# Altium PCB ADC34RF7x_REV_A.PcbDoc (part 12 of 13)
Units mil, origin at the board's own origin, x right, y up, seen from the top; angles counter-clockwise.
Board outline 6250 x 2716.54 mil, 18 copper layers (Top Layer, L2 GND, L3 PWR, L4 GND, L5 PWR/SIG, L6 GND, L7 SIGNAL, L8 GND, L9 GND, L10 SIGNAL, L11 GND, L12 SIGNAL, L13 GND, L14 PWR, L15 GND, L16 PWR/SIG, L16 GND, Bottom Layer), stack 95.314 mil thick; 668 components, 786 nets, 3150 pads, 2020 vias.
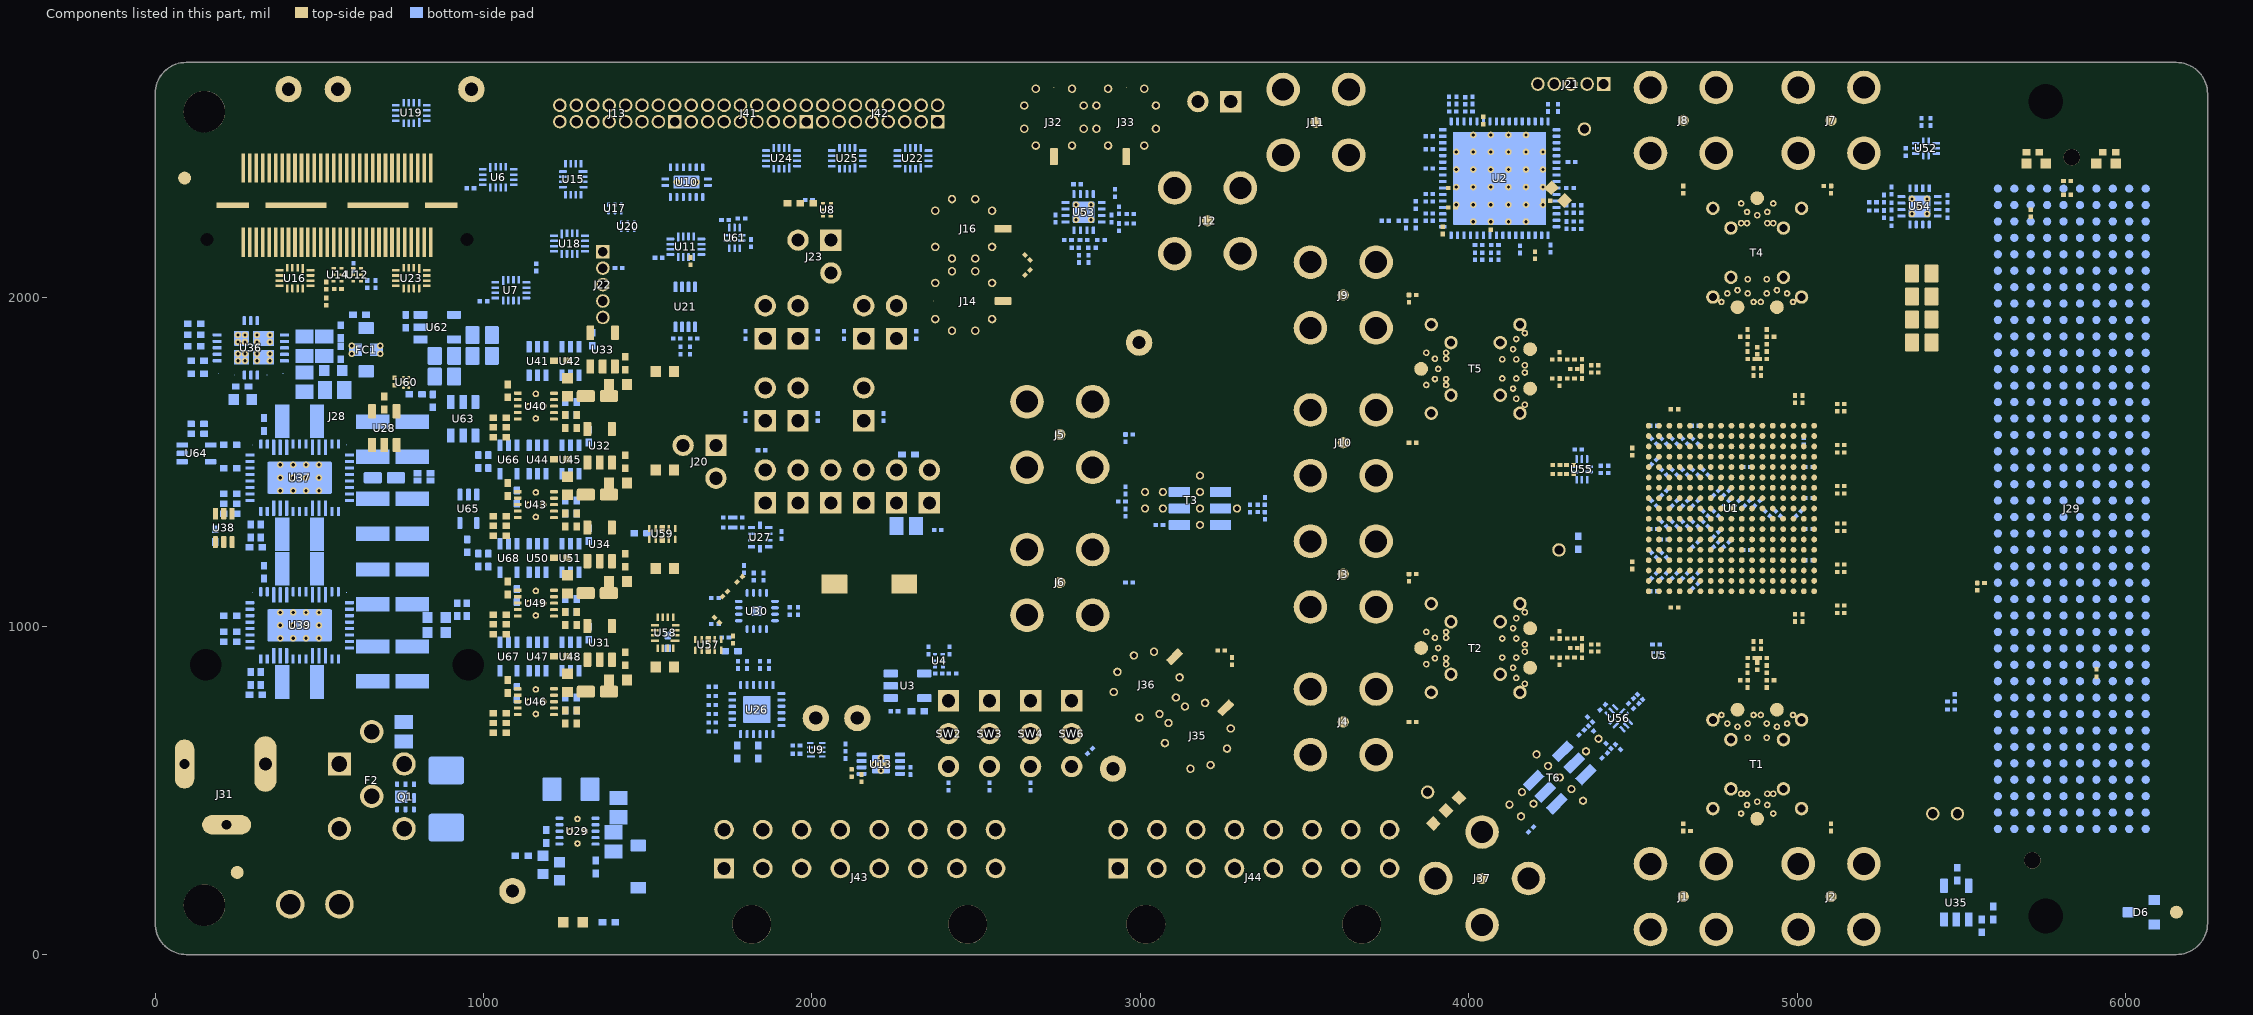
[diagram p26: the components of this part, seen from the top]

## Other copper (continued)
L12 SIGNAL:
  pour cut-out: 1882.62,2561.22 cw(c1882.62,2586.06) 1857.78,2586.06 cw(c1882.62,2586.06) 1882.62,2610.9 cw(c1882.62,2586.06) 1907.46,2586.06 cw(c1882.62,2586.06)
  pour cut-out: 2132.62,2561.22 cw(c2132.62,2586.06) 2107.79,2586.06 cw(c2132.62,2586.06) 2132.62,2610.9 cw(c2132.62,2586.06) 2157.46,2586.06 cw(c2132.62,2586.06)
  pour cut-out: 2082.62,2561.22 cw(c2082.62,2586.06) 2057.79,2586.06 cw(c2082.62,2586.06) 2082.62,2610.9 cw(c2082.62,2586.06) 2107.46,2586.06 cw(c2082.62,2586.06)
  pour cut-out: 1982.62,2561.22 cw(c1982.62,2586.06) 1957.78,2586.06 cw(c1982.62,2586.06) 1982.62,2610.9 cw(c1982.62,2586.06) 2007.46,2586.06 cw(c1982.62,2586.06)
  pour cut-out: 1932.62,2561.22 cw(c1932.62,2586.06) 1907.78,2586.06 cw(c1932.62,2586.06) 1932.62,2610.9 cw(c1932.62,2586.06) 1957.46,2586.06 cw(c1932.62,2586.06)
  pour cut-out: 4203.21,1668.47 cw(c4203.21,1679.47) 4192.21,1679.47 cw(c4203.21,1679.47) 4203.21,1690.47 cw(c4203.21,1679.47) 4214.21,1679.47 cw(c4203.21,1679.47)
  pour cut-out: 4972.22,1744.16 cw(c4972.22,1755.16) 4961.22,1755.16 cw(c4972.22,1755.16) 4972.22,1766.16 cw(c4972.22,1755.16) 4983.22,1755.16 cw(c4972.22,1755.16)
  pour cut-out: 5037.22,1704.16 cw(c5037.22,1715.16) 5026.22,1715.16 cw(c5037.22,1715.16) 5037.22,1726.16 cw(c5037.22,1715.16) 5048.22,1715.16 cw(c5037.22,1715.16)
  pour cut-out: 4972.22,1704.16 cw(c4972.22,1715.16) 4961.22,1715.16 cw(c4972.22,1715.16) 4972.22,1726.16 cw(c4972.22,1715.16) 4983.22,1715.16 cw(c4972.22,1715.16)
  pour cut-out: 4966.23,1665 cw(c4966.23,1676) 4955.23,1676 cw(c4966.23,1676) 4966.23,1687 cw(c4966.23,1676) 4977.23,1676 cw(c4966.23,1676)
  pour cut-out: 4972.22,950.38 cw(c4972.22,961.38) 4961.22,961.38 cw(c4972.22,961.38) 4972.22,972.38 cw(c4972.22,961.38) 4983.22,961.38 cw(c4972.22,961.38)
  pour cut-out: 4957.48,1018.28 cw(c4957.48,1029.28) 4946.48,1029.28 cw(c4957.48,1029.28) 4957.48,1040.28 cw(c4957.48,1029.28) 4968.48,1029.28 cw(c4957.48,1029.28)
  pour cut-out: 4956.83,1056.73 cw(c4956.83,1067.73) 4945.83,1067.73 cw(c4956.83,1067.73) 4956.83,1078.73 cw(c4956.83,1067.73) 4967.83,1067.73 cw(c4956.83,1067.73)
  pour cut-out: 2598.33,1683.28 ccw(c2655,1683.28) 2655,1626.61 ccw(c2655,1683.28) 2711.67,1683.28 ccw(c2655,1683.28) 2655,1739.95 ccw(c2655,1683.28)
  pour cut-out: 2798.33,1683.28 ccw(c2855,1683.28) 2855,1626.61 ccw(c2855,1683.28) 2911.67,1683.28 ccw(c2855,1683.28) 2855,1739.95 ccw(c2855,1683.28)
  pour cut-out: 4987.54,1976.16 cw(c4987.54,1987.16) 4976.54,1987.16 cw(c4987.54,1987.16) 4987.54,1998.16 cw(c4987.54,1987.16) 4998.54,1987.16 cw(c4987.54,1987.16)
  pour cut-out: 5861.42,921.27 cw(c5861.42,932.27) 5850.42,932.27 cw(c5861.42,932.27) 5861.42,943.27 cw(c5861.42,932.27) 5872.42,932.27 cw(c5861.42,932.27)
  pour cut-out: 3907,1965.23 cw(c3907,1976.23) 3896,1976.23 cw(c3907,1976.23) 3907,1987.23 cw(c3907,1976.23) 3918,1976.23 cw(c3907,1976.23)
  pour cut-out: 5003.52,19.66 ccw(c5003.52,76.33) 5060.19,76.33 ccw(c5003.52,76.33) 5003.52,132.99 ccw(c5003.52,76.33) 4946.85,76.33 ccw(c5003.52,76.33)
  pour cut-out: 5203.52,19.66 ccw(c5203.52,76.33) 5260.19,76.33 ccw(c5203.52,76.33) 5203.52,132.99 ccw(c5203.52,76.33) 5146.85,76.33 ccw(c5203.52,76.33)
  pour cut-out: 5003.52,219.66 ccw(c5003.52,276.33) 5060.19,276.33 ccw(c5003.52,276.33) 5003.52,332.99 ccw(c5003.52,276.33) 4946.85,276.33 ccw(c5003.52,276.33)
  pour cut-out: 5203.52,219.66 ccw(c5203.52,276.33) 5260.19,276.33 ccw(c5203.52,276.33) 5203.52,332.99 ccw(c5203.52,276.33) 5146.85,276.33 ccw(c5203.52,276.33)
  pour cut-out: 4301.79,1089.26 cw(c4301.79,1100.26) 4290.79,1100.26 cw(c4301.79,1100.26) 4301.79,1111.26 cw(c4301.79,1100.26) 4312.79,1100.26 cw(c4301.79,1100.26)
  pour cut-out: 5145.95,122.9 cw(c5145.95,133.9) 5134.95,133.9 cw(c5145.95,133.9) 5145.95,144.9 cw(c5145.95,133.9) 5156.95,133.9 cw(c5145.95,133.9)
  pour cut-out: 5961.42,1371.27 cw(c5961.42,1382.27) 5950.42,1382.27 cw(c5961.42,1382.27) 5961.42,1393.27 cw(c5961.42,1382.27) 5972.42,1382.27 cw(c5961.42,1382.27)
  pour cut-out: 5611.42,721.27 cw(c5611.42,732.27) 5600.42,732.27 cw(c5611.42,732.27) 5611.42,743.27 cw(c5611.42,732.27) 5622.42,732.27 cw(c5611.42,732.27)
  pour cut-out: 5661.42,921.27 cw(c5661.42,932.27) 5650.42,932.27 cw(c5661.42,932.27) 5661.42,943.27 cw(c5661.42,932.27) 5672.42,932.27 cw(c5661.42,932.27)
  pour cut-out: 5761.42,921.27 cw(c5761.42,932.27) 5750.42,932.27 cw(c5761.42,932.27) 5761.42,943.27 cw(c5761.42,932.27) 5772.42,932.27 cw(c5761.42,932.27)
  pour cut-out: 5145.97,2571.63 cw(c5145.97,2582.63) 5134.97,2582.63 cw(c5145.97,2582.63) 5145.97,2593.63 cw(c5145.97,2582.63) 5156.97,2582.63 cw(c5145.97,2582.63)
  pour cut-out: 5061.12,2571.63 cw(c5061.12,2582.63) 5050.12,2582.63 cw(c5061.12,2582.63) 5061.12,2593.63 cw(c5061.12,2582.63) 5072.12,2582.63 cw(c5061.12,2582.63)
  pour cut-out: 4695.97,2571.63 cw(c4695.97,2582.63) 4684.97,2582.63 cw(c4695.97,2582.63) 4695.97,2593.63 cw(c4695.97,2582.63) 4706.97,2582.63 cw(c4695.97,2582.63)
  pour cut-out: 4611.12,2571.63 cw(c4611.12,2582.63) 4600.12,2582.63 cw(c4611.12,2582.63) 4611.12,2593.63 cw(c4611.12,2582.63) 4622.12,2582.63 cw(c4611.12,2582.63)
  pour cut-out: 5061.12,2486.78 cw(c5061.12,2497.78) 5050.12,2497.78 cw(c5061.12,2497.78) 5061.12,2508.78 cw(c5061.12,2497.78) 5072.12,2497.78 cw(c5061.12,2497.78)
  pour cut-out: 4685.31,2467.62 cw(c4685.31,2478.62) 4674.31,2478.62 cw(c4685.31,2478.62) 4685.31,2489.62 cw(c4685.31,2478.62) 4696.31,2478.62 cw(c4685.31,2478.62)
  pour cut-out: 4685.58,2332.87 cw(c4685.58,2343.87) 4674.58,2343.87 cw(c4685.58,2343.87) 4685.58,2354.87 cw(c4685.58,2343.87) 4696.58,2343.87 cw(c4685.58,2343.87)
  pour cut-out: 4978.11,1935.7 cw(c4978.11,1946.7) 4967.11,1946.7 cw(c4978.11,1946.7) 4978.11,1957.7 cw(c4978.11,1946.7) 4989.11,1946.7 cw(c4978.11,1946.7)
  pour cut-out: 5203.54,2383.54 ccw(c5203.54,2440.21) 5260.21,2440.21 ccw(c5203.54,2440.21) 5203.54,2496.87 ccw(c5203.54,2440.21) 5146.88,2440.21 ccw(c5203.54,2440.21)
  pour cut-out: 5003.54,2383.54 ccw(c5003.54,2440.21) 5060.21,2440.21 ccw(c5003.54,2440.21) 5003.54,2496.87 ccw(c5003.54,2440.21) 4946.88,2440.21 ccw(c5003.54,2440.21)
  pour cut-out: 4753.54,2383.54 ccw(c4753.54,2440.21) 4810.21,2440.21 ccw(c4753.54,2440.21) 4753.54,2496.87 ccw(c4753.54,2440.21) 4696.88,2440.21 ccw(c4753.54,2440.21)
  pour cut-out: 4553.54,2383.54 ccw(c4553.54,2440.21) 4610.21,2440.21 ccw(c4553.54,2440.21) 4553.54,2496.87 ccw(c4553.54,2440.21) 4496.88,2440.21 ccw(c4553.54,2440.21)
  pour cut-out: 3048.15,2334.21 ccw(c3104.82,2334.21) 3104.82,2277.54 ccw(c3104.82,2334.21) 3161.48,2334.21 ccw(c3104.82,2334.21) 3104.82,2390.87 ccw(c3104.82,2334.21)
  pour cut-out: 3048.15,2134.21 ccw(c3104.82,2134.21) 3104.82,2077.54 ccw(c3104.82,2134.21) 3161.48,2134.21 ccw(c3104.82,2134.21) 3104.82,2190.87 ccw(c3104.82,2134.21)
  pour cut-out: 3461.4,1908.27 ccw(c3518.06,1908.27) 3518.06,1851.6 ccw(c3518.06,1908.27) 3574.73,1908.27 ccw(c3518.06,1908.27) 3518.06,1964.93 ccw(c3518.06,1908.27)
  pour cut-out: 3661.4,1908.27 ccw(c3718.06,1908.27) 3718.06,1851.6 ccw(c3718.06,1908.27) 3774.73,1908.27 ccw(c3718.06,1908.27) 3718.06,1964.93 ccw(c3718.06,1908.27)
  pour cut-out: 5051.97,1599.24 cw(c5051.97,1610.24) 5040.97,1610.24 cw(c5051.97,1610.24) 5051.97,1621.24 cw(c5051.97,1610.24) 5062.97,1610.24 cw(c5051.97,1610.24)
  pour cut-out: 4957.48,1599.24 cw(c4957.48,1610.24) 4946.48,1610.24 cw(c4957.48,1610.24) 4957.48,1621.24 cw(c4957.48,1610.24) 4968.48,1610.24 cw(c4957.48,1610.24)
  pour cut-out: 4831.5,1315.77 cw(c4831.5,1326.77) 4820.5,1326.77 cw(c4831.5,1326.77) 4831.5,1337.77 cw(c4831.5,1326.77) 4842.5,1326.77 cw(c4831.5,1326.77)
  pour cut-out: 4768.5,1252.78 cw(c4768.5,1263.78) 4757.5,1263.78 cw(c4768.5,1263.78) 4768.5,1274.78 cw(c4768.5,1263.78) 4779.5,1263.78 cw(c4768.5,1263.78)
  pour cut-out: 4768.5,1284.28 cw(c4768.5,1295.28) 4757.5,1295.28 cw(c4768.5,1295.28) 4768.5,1306.28 cw(c4768.5,1295.28) 4779.5,1295.28 cw(c4768.5,1295.28)
  pour cut-out: 4768.5,1315.77 cw(c4768.5,1326.77) 4757.5,1326.77 cw(c4768.5,1326.77) 4768.5,1337.77 cw(c4768.5,1326.77) 4779.5,1326.77 cw(c4768.5,1326.77)
  pour cut-out: 4768.5,1347.27 cw(c4768.5,1358.27) 4757.5,1358.27 cw(c4768.5,1358.27) 4768.5,1369.27 cw(c4768.5,1358.27) 4779.5,1358.27 cw(c4768.5,1358.27)
  pour cut-out: 4705.51,1599.24 cw(c4705.51,1610.24) 4694.51,1610.24 cw(c4705.51,1610.24) 4705.51,1621.24 cw(c4705.51,1610.24) 4716.51,1610.24 cw(c4705.51,1610.24)
  pour cut-out: 4642.52,1567.74 cw(c4642.52,1578.74) 4631.52,1578.74 cw(c4642.52,1578.74) 4642.52,1589.74 cw(c4642.52,1578.74) 4653.52,1578.74 cw(c4642.52,1578.74)
  pour cut-out: 4611.02,1473.25 cw(c4611.02,1484.25) 4600.02,1484.25 cw(c4611.02,1484.25) 4611.02,1495.25 cw(c4611.02,1484.25) 4622.02,1484.25 cw(c4611.02,1484.25)
  pour cut-out: 4611.02,1410.26 cw(c4611.02,1421.26) 4600.02,1421.26 cw(c4611.02,1421.26) 4611.02,1432.26 cw(c4611.02,1421.26) 4622.02,1421.26 cw(c4611.02,1421.26)
  pour cut-out: 4611.02,1378.76 cw(c4611.02,1389.76) 4600.02,1389.76 cw(c4611.02,1389.76) 4611.02,1400.76 cw(c4611.02,1389.76) 4622.02,1389.76 cw(c4611.02,1389.76)
  pour cut-out: 4473.75,1293.02 cw(c4473.75,1304.02) 4462.75,1304.02 cw(c4473.75,1304.02) 4473.75,1315.02 cw(c4473.75,1304.02) 4484.75,1304.02 cw(c4473.75,1304.02)
  pour cut-out: 4426.57,1295.82 cw(c4426.57,1306.82) 4415.57,1306.82 cw(c4426.57,1306.82) 4426.57,1317.82 cw(c4426.57,1306.82) 4437.57,1306.82 cw(c4426.57,1306.82)
  pour cut-out: 4298.27,1399.62 cw(c4298.27,1410.62) 4287.27,1410.62 cw(c4298.27,1410.62) 4298.27,1421.62 cw(c4298.27,1410.62) 4309.27,1410.62 cw(c4298.27,1410.62)
  pour cut-out: 4361.04,1832.03 cw(c4361.04,1843.03) 4350.04,1843.03 cw(c4361.04,1843.03) 4361.04,1854.03 cw(c4361.04,1843.03) 4372.04,1843.03 cw(c4361.04,1843.03)
  pour cut-out: 4301.79,1939.24 cw(c4301.79,1950.24) 4290.79,1950.24 cw(c4301.79,1950.24) 4301.79,1961.24 cw(c4301.79,1950.24) 4312.79,1950.24 cw(c4301.79,1950.24)
  pour cut-out: 4116.79,2029.31 cw(c4116.79,2040.31) 4105.79,2040.31 cw(c4116.79,2040.31) 4116.79,2051.31 cw(c4116.79,2040.31) 4127.79,2040.31 cw(c4116.79,2040.31)
  pour cut-out: 4156.1,2118.3 cw(c4156.1,2129.3) 4145.1,2129.3 cw(c4156.1,2129.3) 4156.1,2140.3 cw(c4156.1,2129.3) 4167.1,2129.3 cw(c4156.1,2129.3)
  pour cut-out: 3558.06,1997.27 cw(c3558.06,2008.27) 3547.06,2008.27 cw(c3558.06,2008.27) 3558.06,2019.27 cw(c3558.06,2008.27) 3569.06,2008.27 cw(c3558.06,2008.27)
  pour cut-out: 3661.4,1658.27 ccw(c3718.06,1658.27) 3718.06,1601.6 ccw(c3718.06,1658.27) 3774.73,1658.27 ccw(c3718.06,1658.27) 3718.06,1714.93 ccw(c3718.06,1658.27)
  pour cut-out: 4170,1320 3972.53,1517.47 3972.53,1518.81 4190.26,1518.81 4178.47,1507.02 4178.47,1326.77
  text ".Layer_Name" at 575,-860 h60
L10 SIGNAL:
  pour cut-out: 3897.11,1741.27 cw(c3897.11,1752.27) 3886.11,1752.27 cw(c3897.11,1752.27) 3897.11,1763.27 cw(c3897.11,1752.27) 3908.11,1752.27 cw(c3897.11,1752.27)
  pour cut-out: 3931.11,1741.27 cw(c3931.11,1752.27) 3920.11,1752.27 cw(c3931.11,1752.27) 3931.11,1763.27 cw(c3931.11,1752.27) 3942.11,1752.27 cw(c3931.11,1752.27)
  pour cut-out: 3898.08,1738.93 cw(c3898.08,1749.93) 3887.08,1749.93 cw(c3898.08,1749.93) 3898.08,1760.93 cw(c3898.08,1749.93) 3909.08,1749.93 cw(c3898.08,1749.93)
  pour cut-out: 3897.11,1803.27 cw(c3897.11,1814.27) 3886.11,1814.27 cw(c3897.11,1814.27) 3897.11,1825.27 cw(c3897.11,1814.27) 3908.11,1814.27 cw(c3897.11,1814.27)
  pour cut-out: 3931.11,1803.27 cw(c3931.11,1814.27) 3920.11,1814.27 cw(c3931.11,1814.27) 3931.11,1825.27 cw(c3931.11,1814.27) 3942.11,1814.27 cw(c3931.11,1814.27)
  pour cut-out: 4135.11,1712.27 cw(c4135.11,1723.27) 4124.11,1723.27 cw(c4135.11,1723.27) 4135.11,1734.27 cw(c4135.11,1723.27) 4146.11,1723.27 cw(c4135.11,1723.27)
  pour cut-out: 4171.11,1761.27 cw(c4171.11,1772.27) 4160.11,1772.27 cw(c4171.11,1772.27) 4171.11,1783.27 cw(c4171.11,1772.27) 4182.11,1772.27 cw(c4171.11,1772.27)
  pour cut-out: 4135.11,1832.27 cw(c4135.11,1843.27) 4124.11,1843.27 cw(c4135.11,1843.27) 4135.11,1854.27 cw(c4135.11,1843.27) 4146.11,1843.27 cw(c4135.11,1843.27)
  pour cut-out: 3378.15,2634.21 ccw(c3434.82,2634.21) 3434.82,2577.54 ccw(c3434.82,2634.21) 3491.48,2634.21 ccw(c3434.82,2634.21) 3434.82,2690.87 ccw(c3434.82,2634.21)
  pour cut-out: 3578.15,2634.21 ccw(c3634.82,2634.21) 3634.82,2577.54 ccw(c3634.82,2634.21) 3691.48,2634.21 ccw(c3634.82,2634.21) 3634.82,2690.87 ccw(c3634.82,2634.21)
  pour cut-out: 4433.78,1367.21 cw(c4433.78,1378.21) 4422.78,1378.21 cw(c4433.78,1378.21) 4433.78,1389.21 cw(c4433.78,1378.21) 4444.78,1378.21 cw(c4433.78,1378.21)
  pour cut-out: 4696.88,2640.21 ccw(c4753.54,2640.21) 4753.54,2583.54 ccw(c4753.54,2640.21) 4810.21,2640.21 ccw(c4753.54,2640.21) 4753.54,2696.87 ccw(c4753.54,2640.21)
  pour cut-out: 4496.88,2640.21 ccw(c4553.54,2640.21) 4553.54,2583.54 ccw(c4553.54,2640.21) 4610.21,2640.21 ccw(c4553.54,2640.21) 4553.54,2696.87 ccw(c4553.54,2640.21)
  pour cut-out: 5861.42,2321.27 cw(c5861.42,2332.27) 5850.42,2332.27 cw(c5861.42,2332.27) 5861.42,2343.27 cw(c5861.42,2332.27) 5872.42,2332.27 cw(c5861.42,2332.27)
  pour cut-out: 5811.42,2221.27 cw(c5811.42,2232.27) 5800.42,2232.27 cw(c5811.42,2232.27) 5811.42,2243.27 cw(c5811.42,2232.27) 5822.42,2232.27 cw(c5811.42,2232.27)
  pour cut-out: 5861.42,2121.27 cw(c5861.42,2132.27) 5850.42,2132.27 cw(c5861.42,2132.27) 5861.42,2143.27 cw(c5861.42,2132.27) 5872.42,2132.27 cw(c5861.42,2132.27)
  pour cut-out: 5961.42,1971.27 cw(c5961.42,1982.27) 5950.42,1982.27 cw(c5961.42,1982.27) 5961.42,1993.27 cw(c5961.42,1982.27) 5972.42,1982.27 cw(c5961.42,1982.27)
  pour cut-out: 6061.42,1921.27 cw(c6061.42,1932.27) 6050.42,1932.27 cw(c6061.42,1932.27) 6061.42,1943.27 cw(c6061.42,1932.27) 6072.42,1932.27 cw(c6061.42,1932.27)
  pour cut-out: 6061.42,1971.27 cw(c6061.42,1982.27) 6050.42,1982.27 cw(c6061.42,1982.27) 6061.42,1993.27 cw(c6061.42,1982.27) 6072.42,1982.27 cw(c6061.42,1982.27)
  pour cut-out: 6061.42,2121.27 cw(c6061.42,2132.27) 6050.42,2132.27 cw(c6061.42,2132.27) 6061.42,2143.27 cw(c6061.42,2132.27) 6072.42,2132.27 cw(c6061.42,2132.27)
  pour cut-out: 6061.42,2171.27 cw(c6061.42,2182.27) 6050.42,2182.27 cw(c6061.42,2182.27) 6061.42,2193.27 cw(c6061.42,2182.27) 6072.42,2182.27 cw(c6061.42,2182.27)
  pour cut-out: 6061.42,2321.27 cw(c6061.42,2332.27) 6050.42,2332.27 cw(c6061.42,2332.27) 6061.42,2343.27 cw(c6061.42,2332.27) 6072.42,2332.27 cw(c6061.42,2332.27)
  pour cut-out: 5061.12,2571.63 cw(c5061.12,2582.63) 5050.12,2582.63 cw(c5061.12,2582.63) 5061.12,2593.63 cw(c5061.12,2582.63) 5072.12,2582.63 cw(c5061.12,2582.63)
  pour cut-out: 5145.97,2571.63 cw(c5145.97,2582.63) 5134.97,2582.63 cw(c5145.97,2582.63) 5145.97,2593.63 cw(c5145.97,2582.63) 5156.97,2582.63 cw(c5145.97,2582.63)
  pour cut-out: 4695.97,2571.63 cw(c4695.97,2582.63) 4684.97,2582.63 cw(c4695.97,2582.63) 4695.97,2593.63 cw(c4695.97,2582.63) 4706.97,2582.63 cw(c4695.97,2582.63)
  pour cut-out: 4611.12,2571.63 cw(c4611.12,2582.63) 4600.12,2582.63 cw(c4611.12,2582.63) 4611.12,2593.63 cw(c4611.12,2582.63) 4622.12,2582.63 cw(c4611.12,2582.63)
  pour cut-out: 4361.07,2573.95 cw(c4361.07,2584.95) 4350.07,2584.95 cw(c4361.07,2584.95) 4361.07,2595.95 cw(c4361.07,2584.95) 4372.07,2584.95 cw(c4361.07,2584.95)
  pour cut-out: 1214.61,709.43 cw(c1214.61,720.43) 1203.61,720.43 cw(c1214.61,720.43) 1214.61,731.43 cw(c1214.61,720.43) 1225.61,720.43 cw(c1214.61,720.43)
  pour cut-out: 1431.18,909.24 cw(c1431.18,920.24) 1420.18,920.24 cw(c1431.18,920.24) 1431.18,931.24 cw(c1431.18,920.24) 1442.18,920.24 cw(c1431.18,920.24)
  pour cut-out: 1214.61,1009.43 cw(c1214.61,1020.43) 1203.61,1020.43 cw(c1214.61,1020.43) 1214.61,1031.43 cw(c1214.61,1020.43) 1225.61,1020.43 cw(c1214.61,1020.43)
  pour cut-out: 1214.61,1309.43 cw(c1214.61,1320.43) 1203.61,1320.43 cw(c1214.61,1320.43) 1214.61,1331.43 cw(c1214.61,1320.43) 1225.61,1320.43 cw(c1214.61,1320.43)
  pour cut-out: 1214.61,1609.43 cw(c1214.61,1620.43) 1203.61,1620.43 cw(c1214.61,1620.43) 1214.61,1631.43 cw(c1214.61,1620.43) 1225.61,1620.43 cw(c1214.61,1620.43)
  pour cut-out: 4946.85,76.33 ccw(c5003.52,76.33) 5003.52,19.66 ccw(c5003.52,76.33) 5060.19,76.33 ccw(c5003.52,76.33) 5003.52,132.99 ccw(c5003.52,76.33)
  pour cut-out: 5146.85,76.33 ccw(c5203.52,76.33) 5203.52,19.66 ccw(c5203.52,76.33) 5260.19,76.33 ccw(c5203.52,76.33) 5203.52,132.99 ccw(c5203.52,76.33)
  pour cut-out: 4946.85,276.33 ccw(c5003.52,276.33) 5003.52,219.66 ccw(c5003.52,276.33) 5060.19,276.33 ccw(c5003.52,276.33) 5003.52,332.99 ccw(c5003.52,276.33)
  pour cut-out: 5146.85,276.33 ccw(c5203.52,276.33) 5203.52,219.66 ccw(c5203.52,276.33) 5260.19,276.33 ccw(c5203.52,276.33) 5203.52,332.99 ccw(c5203.52,276.33)
  pour cut-out: 3661.4,1658.27 ccw(c3718.06,1658.27) 3718.06,1601.6 ccw(c3718.06,1658.27) 3774.73,1658.27 ccw(c3718.06,1658.27) 3718.06,1714.93 ccw(c3718.06,1658.27)
  pour cut-out: 3555.09,1382.97 cw(c3555.09,1393.97) 3544.09,1393.97 cw(c3555.09,1393.97) 3555.09,1404.97 cw(c3555.09,1393.97) 3566.09,1393.97 cw(c3555.09,1393.97)
  pour cut-out: 3475.09,1382.97 cw(c3475.09,1393.97) 3464.09,1393.97 cw(c3475.09,1393.97) 3475.09,1404.97 cw(c3475.09,1393.97) 3486.09,1393.97 cw(c3475.09,1393.97)
  pour cut-out: 3461.4,1908.27 ccw(c3518.06,1908.27) 3518.06,1851.6 ccw(c3518.06,1908.27) 3574.73,1908.27 ccw(c3518.06,1908.27) 3518.06,1964.93 ccw(c3518.06,1908.27)
  pour cut-out: 3661.4,1908.27 ccw(c3718.06,1908.27) 3718.06,1851.6 ccw(c3718.06,1908.27) 3774.73,1908.27 ccw(c3718.06,1908.27) 3718.06,1964.93 ccw(c3718.06,1908.27)
  pour cut-out: 3661.4,1258.29 ccw(c3718.06,1258.29) 3718.06,1201.62 ccw(c3718.06,1258.29) 3774.73,1258.29 ccw(c3718.06,1258.29) 3718.06,1314.96 ccw(c3718.06,1258.29)
  pour cut-out: 3461.4,1258.29 ccw(c3518.06,1258.29) 3518.06,1201.62 ccw(c3518.06,1258.29) 3574.73,1258.29 ccw(c3518.06,1258.29) 3518.06,1314.96 ccw(c3518.06,1258.29)
  pour cut-out: 3661.4,1458.27 ccw(c3718.06,1458.27) 3718.06,1401.6 ccw(c3718.06,1458.27) 3774.73,1458.27 ccw(c3718.06,1458.27) 3718.06,1514.93 ccw(c3718.06,1458.27)
  pour cut-out: 3461.4,1458.27 ccw(c3518.06,1458.27) 3518.06,1401.6 ccw(c3518.06,1458.27) 3574.73,1458.27 ccw(c3518.06,1458.27) 3518.06,1514.93 ccw(c3518.06,1458.27)
  pour cut-out: 3461.4,1658.27 ccw(c3518.06,1658.27) 3518.06,1601.6 ccw(c3518.06,1658.27) 3574.73,1658.27 ccw(c3518.06,1658.27) 3518.06,1714.93 ccw(c3518.06,1658.27)
  pour cut-out: 5020.47,1126.8 cw(c5020.47,1137.8) 5009.47,1137.8 cw(c5020.47,1137.8) 5020.47,1148.8 cw(c5020.47,1137.8) 5031.47,1137.8 cw(c5020.47,1137.8)
  pour cut-out: 5020.47,1567.74 cw(c5020.47,1578.74) 5009.47,1578.74 cw(c5020.47,1578.74) 5020.47,1589.74 cw(c5020.47,1578.74) 5031.47,1578.74 cw(c5020.47,1578.74)
  pour cut-out: 4768.5,1347.27 cw(c4768.5,1358.27) 4757.5,1358.27 cw(c4768.5,1358.27) 4768.5,1369.27 cw(c4768.5,1358.27) 4779.5,1358.27 cw(c4768.5,1358.27)
  pour cut-out: 4610.44,1126.53 cw(c4610.44,1137.53) 4599.44,1137.53 cw(c4610.44,1137.53) 4610.44,1148.53 cw(c4610.44,1137.53) 4621.44,1137.53 cw(c4610.44,1137.53)
  pour cut-out: 4674.02,1126.8 cw(c4674.02,1137.8) 4663.02,1137.8 cw(c4674.02,1137.8) 4674.02,1148.8 cw(c4674.02,1137.8) 4685.02,1137.8 cw(c4674.02,1137.8)
  pour cut-out: 4426.57,1295.82 cw(c4426.57,1306.82) 4415.57,1306.82 cw(c4426.57,1306.82) 4426.57,1317.82 cw(c4426.57,1306.82) 4437.57,1306.82 cw(c4426.57,1306.82)
  pour cut-out: 4705.51,1599.24 cw(c4705.51,1610.24) 4694.51,1610.24 cw(c4705.51,1610.24) 4705.51,1621.24 cw(c4705.51,1610.24) 4716.51,1610.24 cw(c4705.51,1610.24)
  pour cut-out: 4548.03,1567.74 cw(c4548.03,1578.74) 4537.03,1578.74 cw(c4548.03,1578.74) 4548.03,1589.74 cw(c4548.03,1578.74) 4559.03,1578.74 cw(c4548.03,1578.74)
  pour cut-out: 4685.58,2179.41 cw(c4685.58,2190.41) 4674.58,2190.41 cw(c4685.58,2190.41) 4685.58,2201.41 cw(c4685.58,2190.41) 4696.58,2190.41 cw(c4685.58,2190.41)
  pour cut-out: 4326.55,2323.15 cw(c4326.55,2334.15) 4315.55,2334.15 cw(c4326.55,2334.15) 4326.55,2345.15 cw(c4326.55,2334.15) 4337.55,2334.15 cw(c4326.55,2334.15)
  pour cut-out: 3558.06,1997.27 cw(c3558.06,2008.27) 3547.06,2008.27 cw(c3558.06,2008.27) 3558.06,2019.27 cw(c3558.06,2008.27) 3569.06,2008.27 cw(c3558.06,2008.27)
  pour cut-out: 3618.06,1937.27 cw(c3618.06,1948.27) 3607.06,1948.27 cw(c3618.06,1948.27) 3618.06,1959.27 cw(c3618.06,1948.27) 3629.06,1948.27 cw(c3618.06,1948.27)
  pour cut-out: 3660.49,1954.84 cw(c3660.49,1965.84) 3649.49,1965.84 cw(c3660.49,1965.84) 3660.49,1976.84 cw(c3660.49,1965.84) 3671.49,1965.84 cw(c3660.49,1965.84)
  pour cut-out: 3775.26,1965.23 cw(c3775.26,1976.23) 3764.26,1976.23 cw(c3775.26,1976.23) 3775.26,1987.23 cw(c3775.26,1976.23) 3786.26,1976.23 cw(c3775.26,1976.23)
  pour cut-out: 3786.02,1944.05 cw(c3786.02,1955.05) 3775.02,1955.05 cw(c3786.02,1955.05) 3786.02,1966.05 cw(c3786.02,1955.05) 3797.02,1955.05 cw(c3786.02,1955.05)
  pour cut-out: 3907,1965.23 cw(c3907,1976.23) 3896,1976.23 cw(c3907,1976.23) 3907,1987.23 cw(c3907,1976.23) 3918,1976.23 cw(c3907,1976.23)
  pour cut-out: 3987,1965.23 cw(c3987,1976.23) 3976,1976.23 cw(c3987,1976.23) 3987,1987.23 cw(c3987,1976.23) 3998,1976.23 cw(c3987,1976.23)
  pour cut-out: 4067,1965.23 cw(c4067,1976.23) 4056,1976.23 cw(c4067,1976.23) 4067,1987.23 cw(c4067,1976.23) 4078,1976.23 cw(c4067,1976.23)
  pour cut-out: 4234.52,1773.09 cw(c4234.52,1784.09) 4223.52,1784.09 cw(c4234.52,1784.09) 4234.52,1795.09 cw(c4234.52,1784.09) 4245.52,1784.09 cw(c4234.52,1784.09)
  pour cut-out: 4200.97,1788.43 cw(c4200.97,1799.43) 4189.97,1799.43 cw(c4200.97,1799.43) 4200.97,1810.43 cw(c4200.97,1799.43) 4211.97,1799.43 cw(c4200.97,1799.43)
  pour cut-out: 4134.52,1579.31 cw(c4134.52,1590.31) 4123.52,1590.31 cw(c4134.52,1590.31) 4134.52,1601.31 cw(c4134.52,1590.31) 4145.52,1590.31 cw(c4134.52,1590.31)
  pour cut-out: 4054.52,1579.31 cw(c4054.52,1590.31) 4043.52,1590.31 cw(c4054.52,1590.31) 4054.52,1601.31 cw(c4054.52,1590.31) 4065.52,1590.31 cw(c4054.52,1590.31)
  pour cut-out: 3974.52,1579.31 cw(c3974.52,1590.31) 3963.52,1590.31 cw(c3974.52,1590.31) 3974.52,1601.31 cw(c3974.52,1590.31) 3985.52,1590.31 cw(c3974.52,1590.31)
  pour cut-out: 3894.52,1579.31 cw(c3894.52,1590.31) 3883.52,1590.31 cw(c3894.52,1590.31) 3894.52,1601.31 cw(c3894.52,1590.31) 3905.52,1590.31 cw(c3894.52,1590.31)
  pour cut-out: 3779.86,1579.31 cw(c3779.86,1590.31) 3768.86,1590.31 cw(c3779.86,1590.31) 3779.86,1601.31 cw(c3779.86,1590.31) 3790.86,1590.31 cw(c3779.86,1590.31)
  pour cut-out: 3699.86,1579.31 cw(c3699.86,1590.31) 3688.86,1590.31 cw(c3699.86,1590.31) 3699.86,1601.31 cw(c3699.86,1590.31) 3710.86,1590.31 cw(c3699.86,1590.31)
  pour cut-out: 1802,1782 1802,2186.87 2541.03,2186.87 2541.03,2186.1
  pour cut-out: 1930,2270 1932.62,2267.38 1932.62,2175.08 2057.48,2175.08 2057.76,2175.36 1960.34,2272.78 1932.62,2272.78
  pour cut-out: 1175.35,2162.13 1930.89,2162.13 1930.89,2505.56 2390.45,2505.56 2390.45,2626.34 1175.35,2626.34
  pour cut-out: 1800,2050 1643.82,2206.18 1805.73,2206.18
  text ".Layer_Name" at 575,-860 h60
L11 GND:
  text ".Layer_Name" at 575,-860 h60
L13 GND:
  text ".Layer_Name" at 575,-860 h60
Bottom Layer:
  drawing of 87 lines, arcs and shapes, not listed
  text ".Layer_Name" at 577,-858.49 h60
Multi-Layer:
  pour cut-out: 3186.77,2234.21 ccw(c3204.82,2234.21) 3204.82,2216.16 ccw(c3204.82,2234.21) 3222.86,2234.21 ccw(c3204.82,2234.21) 3204.82,2252.25 ccw(c3204.82,2234.21)
  pour cut-out: 3516.77,2534.21 ccw(c3534.82,2534.21) 3534.82,2516.16 ccw(c3534.82,2534.21) 3552.86,2534.21 ccw(c3534.82,2534.21) 3534.82,2552.25 ccw(c3534.82,2534.21)
  pour cut-out: 2736.96,1583.28 ccw(c2755,1583.28) 2755,1565.23 ccw(c2755,1583.28) 2773.04,1583.28 ccw(c2755,1583.28) 2755,1601.32 ccw(c2755,1583.28)
  pour cut-out: 2736.96,1133.28 ccw(c2755,1133.28) 2755,1115.23 ccw(c2755,1133.28) 2773.04,1133.28 ccw(c2755,1133.28) 2755,1151.32 ccw(c2755,1133.28)
  pour cut-out: 4022.7,231.61 ccw(c4040.75,231.61) 4040.75,213.57 ccw(c4040.75,231.61) 4058.79,231.61 ccw(c4040.75,231.61) 4040.75,249.66 ccw(c4040.75,231.61)

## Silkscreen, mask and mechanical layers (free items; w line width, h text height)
Top Overlay:
  drawing of 157 lines, arcs and shapes, not listed
  text "LMK SPI" at 3961.29,2634.21 h25
  text "<-GND" at 2425.78,2569.08 h25
  text "GND->" at 1066.12,2566.54 h25
  text "Power Supply OK" at 5494.27,2341 h25
  text "DUT OPTION" at 5320,2105 h100
  text "ADC SPI" at 1114.17,2073.52 h25
  text "ADC34RF72" at 5455,2045 h50
  text "ADC34RF75" at 5455,1975 h50
  text "ADC32RF77" at 5455,1905 h50
  text "Other" at 5455,1835 h50
  text "GPIOVDD" at 1561.4,1654.84 h25
  text "FPGA to ADC" at 2369.72,855.04 h25
  text "3.3V" at 2742.94,854.43 h25
  text "ADC3xRF7x / RevA" at 3376.97,466.84 h60
  text "ADC to FPGA" at 2365.49,450.75 h25
  text "I2C VADJ" at 2741,421.68 h25
  text "VADJ" at 3985.19,408.16 h30 r45
  text "<- GND ->" at 2627.33,331.11 h25
  text "GND->" at 1520.86,328.55 h25
  text "GPIO" at 3885.07,309.5 h30 r45
  text "AVDD12" at 2278.53,190.01 h20
  text "AVDD18" at 2907.83,190.01 h20
  text "DVDD09" at 1685.9,186.52 h20
  text "AVDD12 / SNS" at 2486.89,151.03 h20
  text "AVDD18 / SNS" at 3096.34,151.03 h20
  text "CLK / VDD12" at 3343.68,148.9 h20
  text "CLK / VDD18" at 3579.9,148.9 h20
  text "DVDD / SNS+" at 2132.53,148.17 h20
  text "DVDD / SNS-" at 3214.42,148.17 h20
  text "CLK / VDD12 / SNS" at 3448.27,132.78 h20
  text "CLK / VDD18 / SNS" at 3684.49,132.78 h20
  text "CW" at 6110.58,34.15 h40
  text "Connector #1" at 1817.12,6.09 h25
  text "Connector #2" at 3017.12,6.09 h25
  text ".Layer_Name" at 577,-858.49 h60
Bottom Overlay:
  circle w10: c1740.4,684.59 r0.08
  lines w4: 2624.7,413.68 2613.7,421.68 ; 2624.7,429.68 2613.7,421.68 ; 2628.92,320.88 2617.92,328.88 ; 2628.92,336.88 2617.92,328.88 ; 2667.7,421.68 2613.7,421.68 ; 2671.92,328.88 2617.92,328.88 ; 2776.7,421.68 2830.7,421.68 ; 2780.92,328.88 2834.92,328.88 ; 2819.7,413.68 2830.7,421.68 ; 2819.7,429.68 2830.7,421.68 ; 2823.92,320.88 2834.92,328.88 ; 2823.92,336.88 2834.92,328.88
  lines w7: 990,1555 1005,1540 ; 1020,1555 1005,1540 ; 1040,1600 1005,1565 1005,1540
  text "OUTER / GNDS" at 2788.11,386.45 h25
  text "INNER / PWR" at 2786.31,296.55 h25
  text ".Layer_Name" at 577,-858.49 h60
Top Paste:
  text ".Layer_Name" at 577,-858.49 h60
Bottom Paste:
  text ".Layer_Name" at 577,-858.49 h60
Top Solder:
  text ".Layer_Name" at 577,-858.49 h60
  text ".Layer_Name" at 577,-858.49 h60
Bottom Solder:
  text ".Layer_Name" at 577,-858.49 h60
Drill Guide:
  text ".Layer_Name" at 577,-858.49 h60
M1 Board Outline:
  the board outline again, w10
  text ".Layer_Name" at 577,-858.49 h60
M2 Board Dimensions:
  rectangle: 125,-400 500,-275
  rectangle: 0,-275 125,-150
  lines w7: 0,-275 1000,-275 ; 125,-400 125,-150 ; 250,-400 250,-150 ; 500,-400 500,-150 ; 750,-400 750,-150 ; 0,-400 0,-150 1000,-150 1000,-400 0,-400
  text ".Layer_Name" at 577,-858.49 h60
M3 3D STEP Top:
  text ".Layer_Name" at 577,-858.49 h60
M4 3D STEP Bottom:
  text ".Layer_Name" at 577,-858.49 h60
M5 Assembly Top:
  lines w10: -292,-930.17 6308,-930.17 ; -292,-726.83 6310,-726.83 ; -292,-523.5 -292,-1133.5 3713,-1133.5 6310,-1133.5 6310,-523.5 -291.5,-523.5 -291.5,-1133.5 1284,-1133.5 ; 2173,-1133.5 2173,-523.5 ; 3440,-726.83 3440,-523.5 ; 4280,-726.83 4280,-523.5 ; 4902,-1140 4902,-937.17
  text "COMPONENTS MARKED 'DNP' SHOULD NOT BE POPULATED." at 1153.5,-318.5 h60
  text "ASSEMBLY VARIANT:" at 1153,-434 h60
  text ".VariantName" at 2189,-434 h60
  text "PCB VIEWED FROM TOP SIDE" at -228.5,-655.67 h60
  text "BOARD #:" at 2248,-655.67 h60
  text ".PRJ_Number" at 2793.5,-655.67 h60
  text "REV:" at 3638,-655.67 h60
  text ".PCB_Rev" at 3929.5,-655.67 h60
  text "SVN REV:" at 4476,-655.67 h60
  text ".VersionControl_RevNumber" at 4982,-655.67 h60
  text "PLOT NAME =" at -228.5,-1064.34 h60
  text ".plot_File_Name" at 577,-1064.34 h60
  text "GENERATED    :" at 2250,-1064.34 h60
  text ".Print_Date" at 3119.5,-1064.34 h60
  text ".Print_Time" at 3848.5,-1064.34 h60
  text "TEXAS INSTRUMENTS" at 5113,-1064.34 h60
M6 Assembly Bottom:
  lines w10: -292.5,-727.33 6309.5,-727.33 ; -290.5,-930.67 6309.5,-930.67 ; 1115.5,-1140.5 1115.5,-937.67 ; 1737.5,-727.33 1737.5,-524 ; 2577.5,-727.33 2577.5,-524 ; 3844.5,-1134 3844.5,-524 ; 4733.5,-1134 6309,-1134 6309,-524 -292.5,-524 -292.5,-1134 2304.5,-1134 6309.5,-1134 6309.5,-524
  text "COMPONENTS MARKED 'DNP' SHOULD NOT BE POPULATED." at 6102,-318 h60
  text ".VariantName" at 5058,-434 h60
  text "ASSEMBLY VARIANT:" at 6097,-434 h60
  text ".VersionControl_RevNumber" at 1035.5,-656.17 h60
  text "SVN REV:" at 1541.5,-656.17 h60
  text ".PCB_Rev" at 2088,-656.17 h60
  text "REV:" at 2379.5,-656.17 h60
  text ".PRJ_Number" at 3224,-656.17 h60
  text "BOARD #:" at 3769.5,-656.17 h60
  text "PCB VIEWED FROM BOTTOM SIDE" at 6246,-656.17 h60
  text "TEXAS INSTRUMENTS" at 904.5,-1064.84 h60
  text ".Print_Time" at 2169,-1064.84 h60
  text ".Print_Date" at 2898,-1064.84 h60
  text "GENERATED    :" at 3767.5,-1064.84 h60
  text ".plot_File_Name" at 5440.5,-1064.84 h60
  text "PLOT NAME =" at 6246,-1064.84 h60
M9 Title Sheet:
  drawing of 56 lines, arcs and shapes, not listed
  text "1" at 1058.34,13381.39 h70
  text "2" at 4384,13381.39 h70
  text "3" at 7714,13381.39 h70
  text "4" at 11049,13381.39 h70
  text "5" at 14374,13381.39 h70
  text "6" at 17709,13381.39 h70
  text "A" at -463,11603.39 h70
  text "A" at 19237,11603.39 h70
  text "B" at -463,7853.39 h70
  text "B" at 19237,7853.39 h70
  text "C" at -463,4103.39 h70
  text "C" at 19237,4103.39 h70
  text "D" at -463,353.39 h70
  text "D" at 19237,353.39 h70
  text "PROJECT TITLE:" at 16143,268.39 h45
  text ".PRJ_Title" at 16193,135.06 h70
  text "DESIGNED FOR:" at 16143,-32.61 h45
  text ".PRJ_Customer" at 16193,-172.61 h70
  text "FILE NAME:" at 16143,-332.61 h45
  text ".PCB_File_Name_No_Path" at 16193,-452.61 h70
  text "Texas Instruments (TI) and/or its licensors do not warrant the accuracy or completeness of this specification" at 11173.5,-614.45 h45
  text "ENGINEER:" at 16143,-622.61 h45
  text "LAYOUT BY:" at 17648,-622.61 h45
  text "or any information contained therein. TI and/or its licensors do not warrant that this design will meet" at 11128.51,-727.11 h45
  text ".PRJ_Engineer" at 16193,-777.6 h70
  text ".PCB_Layout" at 17698.5,-777.6 h70
  text "the specifications, will be suitable for your application or fit for any particular purpose, or will operate in" at 11128.51,-839.78 h45
  text ".Layer_Name" at 577,-858.49 h60
  text "ALTIUM DESIGNER VERSION:" at 17648,-932.61 h45
  text "an implementation. TI and/or its licensors do not warrant that the design is production worthy. You should" at 11128.51,-952.44 h45
  text "completely validate and test your design implementation to confirm the system functionality for your application." at 11173.5,-1065.11 h45
  text ".print_Scale" at 16193,-1065.94 h70
  text ".Application_BuildNumber" at 17698.5,-1065.94 h70
  text "1" at 1058.34,-1318.61 h70
  text "2" at 4384,-1318.61 h70
  text "3" at 7714,-1318.61 h70
  text "4" at 11049,-1318.61 h70
  text "5" at 14374,-1318.61 h70
  text "6" at 17709,-1318.61 h70
M10 Fab Notes:
  drawing of 209 lines, arcs and shapes, not listed
  text "M10 Fab Notes" at 16103.69,8035.93 h60
  text "DESIGN INFORMATION" at 17182.02,7918.81 h60
  text "MIN. TRACK WIDTH:" at 16537.46,7786.68 h60
  text "3.5" at 17579,7786 h60
  text "MIL" at 17788.46,7786.68 h60
  text "MIN. CLEARANCE:" at 16537.46,7662.55 h60
  text "MIL" at 17788.46,7662.55 h60
  text "4" at 17633.92,7660.91 h60
  text "MIN. VIA PAD SIZE:" at 16537.46,7538.43 h60
  text "20" at 17603.71,7538.43 h60
  text "MIL" at 17788.46,7538.43 h60
  text "0.05mm (2MIL)" at 17232.46,7408.53 h60
  text "MINIMUM ANNULAR RING" at 16208.23,7400.31 h60
  text "EXTERNAL" at 17940.46,7400.31 h60
  text "PER" at 16408.23,7290.18 h60
  text "IPC-D-275 CLASS 2 LEVEL C" at 16628.23,7290.18 h60
  text "MIL, HOLES" at 18116.46,7189.7 h60
  text "+/-" at 17724,7181.11 h60
  text "+/-" at 18578,7181.11 h60
  text "REGISTRATION TOLERANCES:" at 16208.23,7180.05 h60
  text "METAL" at 17408,7180.05 h60
  text "5" at 17984.2,7180.05 h60
  text "3" at 18817.2,7180.05 h60
  text "MIL" at 18933.46,7180.05 h60
  text "HOLE SIZE TOLERANCE (UNLESS OTHERWISE SPECIFIED):" at 16208.23,7081.73 h60
  text "+/-" at 18578,7078.86 h60
  text "3" at 18817.2,7077.8 h60
  text "MIL" at 18933.46,7077.8 h60
  text "MATERIAL:" at 16133.46,6940.15 h60
  text "UNIFORM STACKUP" at 17867.51,6845.23 h60
  text "HYBRID STACKUP" at 16841.98,6837.95 h60
  text "X" at 16697.81,6830.94 h60
  text "ISOLA FR4-370HR" at 16548.18,6674.31 h60
  text "X" at 16404,6667.3 h60
  text "Megtron 4    Isola I-Speed" at 16539.43,6473.06 h60
  text "OR" at 16989.42,6473.06 h60
  text "X" at 16405.01,6280.16 h60
  text "Megtron6    Isola MT-40    Nelco MW-1000" at 16539.43,6276.21 h60
  text "OR" at 16940.78,6276.21 h60
  text "OR" at 17639.51,6276.21 h60
  text "OTHER" at 16579.43,6079.36 h60
  text "X" at 18054,5890 h60
  text "62 MIL (1.6mm) +/-10%" at 16877.71,5881.78 h60
  text "96 MIL  +/-10%" at 18453.68,5881.78 h60
  text "THICKNESS:" at 16211.38,5873.55 h60
  text "OTHER" at 18162.61,5873.55 h60
  text "TOLERANCE:" at 16211.38,5735.24 h60
  text "X" at 17059.61,5735.24 h60
  text "ANSI IPC-6012 TYPE 3 CLASS 2" at 17237.62,5735.24 h60
  text "OTHER +/-" at 17237.61,5591.05 h60
  text "BOW & TWIST:" at 16211.38,5445.86 h60
  text "X" at 17059.61,5445.86 h60
  text "ANSI IPC-6012 TYPE 3 CLASS 2" at 17237.62,5445.86 h60
  text "OTHER +/-" at 17237.61,5299.17 h60
  text "DRILLING:" at 16136.61,5168.55 h60
  text "NC_DRILL FILES" at 17897.61,5063.36 h60
  text "REFERENCE:" at 16211.38,5059.42 h60
  text "X" at 16868.61,5059.32 h60
  text "AS SHOWN" at 17046.61,5059.42 h60
  text "X" at 17769.61,5059.42 h60
  text "OTHER" at 18195.61,4917.17 h60
  text "PTH COPPER THICKNESS:" at 16211.05,4913.64 h60
  text "X" at 17350.29,4913.64 h60
  text "20-30 um" at 17478.29,4913.64 h60
  text "BOARD FINISH:" at 16136.61,4766.04 h60
  text "SILKSCREEN:" at 16291.83,4655.92 h60
  text "X" at 17249.61,4655.92 h60
  text "TOP" at 17366.61,4655.92 h60
  text "X" at 17759.61,4655.92 h60
  text "BOTTOM" at 17877.61,4655.92 h60
  text "SILKSCREEN COLOR:" at 16291.83,4500.73 h60
  text "X" at 17249.61,4500.73 h60
  text "WHITE" at 17366.61,4500.73 h60
  text "OTHER" at 17877.61,4500.73 h60
  text "DARK GREEN" at 18483.4,4363.41 h60
  text "X" at 17972.29,4360.69 h60
  text "GREEN" at 17497.61,4357.28 h60
  text "OTHER" at 18115.61,4357.28 h60
  text "SOLDER RESIST COLOR:" at 16291.83,4350.41 h60
  text "X" at 17379.61,4203.03 h60
  text "MATTE" at 17497.61,4203.03 h60
  text "SEMI-GLOSS" at 18115.15,4202.39 h60
  text "X" at 17009.84,4030.26 h60
  text "IMMERSION GOLD (ENIG)" at 17197.61,4030.26 h60
  text "ENEPIG" at 18535.15,4023.03 h60
  text "SURFACE FINISH:" at 16136.61,4022.03 h60
  text "IMM. TIN/SILVER OR EQUIV" at 16466.15,3884.72 h60
  text "HARD GOLD (30u)" at 17897.61,3880.78 h60
  text "OTHER" at 16491.15,3683.93 h60
  text "ARRAY/PANEL:" at 16136.61,3528.55 h60
  text "CUT AND TRIM PER M1 BOARD OUTLINE" at 17197.61,3520.33 h60
  text "N.C. ROUTE" at 17197.61,3384.36 h60
  text "X" at 17885.61,3384.36 h60
  text "V. SCORE" at 18063.61,3384.36 h60
  text "CERTIFICATION:" at 16136.61,3255.24 h60
  text "MATERIALS AND WORKMANSHIP FOR ALL PCBS" at 16861.61,3255.24 h60
  text "TO MEET OR EXCEED THE REQUIREMENTS OF:" at 16861.61,3161.18 h60
  text "X" at 16499.12,3032.55 h60
  text "ANSI IPC-A-600F CLASS ->" at 16627.11,3032.55 h60
  text "X" at 18275.12,3032.55 h60
  text "2" at 18385.11,3032.55 h60
  text "1" at 18070.11,3031.05 h60
  text "3" at 18739.11,3031.05 h60
  text "X" at 17311.12,2884.86 h60
  text "RoHS" at 17439.11,2884.86 h60
  text "OTHER" at 18083.51,2884.86 h60
  text "PER ORDER" at 18480.57,2884.86 h60
  text "ALL BOARDS MUST MEET OR EXCEED UL94-V0 REQUIREMENTS." at 16164.15,2731.03 h60
  text "PCB MUST BEAR THE UL94V-0 UL REGISTERED MATERIAL ID NUMBER" at 16164.15,2614.97 h60
  text "ADDITIONAL REQUIREMENTS:" at 16136.61,2445.55 h60
  text "MICROSECTION:" at 16211.38,2338.42 h60
  text "YES" at 17117.11,2338.42 h60
  text "REQUIRED" at 17978.61,2194.09 h60
  text "BARE BOARD ELEC. TEST:" at 16211.38,2191.23 h60
  text "NONE" at 17517.11,2191.23 h60
  text "X" at 17860.61,2191.23 h60
  text "PER ORDER" at 18570.61,2191.23 h60
  text "X" at 16255.91,1999.02 h60
  text "16 MIL & SMALLER VIAS REQUIRE NON-CONDUCTIVE FILL AND PLANARIZE" at 16363.45,1910.22 h59
  text "X" at 16254.91,1801.02 h60
  text "OUTER LAYER TRACKS 12.1 MIL WIDE REQUIRE 50 OHM SINGLE-ENDED IMPEDANCE" at 16366.4,1699.59 h60
  text "X" at 16260.91,1598.02 h60
  text "OUTER LAYER TRACKS 7.4 MIL WIDE WITH 5 MIL SPACE REQUIRE 100 OHM DIFFERENTIAL IMPEDANCE" at 16366.4,1494.87 h60
  text "INNER LAYERS TRACKS XX MIL WIDE REQUIRE 50 OHM SINGLE-ENDED IMPEDANCE" at 16366.4,1290.14 h60
  text "X" at 16260,1189 h60
  text "INNER LAYER TRACKS 3.5 MIL WIDE WITH  6.5 MIL SPACE REQUIRE 100 OHM DIFFERENTIAL IMPEDANCE" at 16361,1052 h60
  text ".Layer_Name" at 577,-858.49 h60
M11 Gerber Information:
  lines w10: -292,-930.17 6308,-930.17 ; -292,-726.83 6310,-726.83 ; -292,-523.5 -292,-1133.5 3713,-1133.5 6310,-1133.5 6310,-523.5 -291.5,-523.5 -291.5,-1133.5 1284,-1133.5 ; 2173,-1133.5 2173,-523.5 ; 3440,-726.83 3440,-523.5 ; 4280,-726.83 4280,-523.5 ; 4902,-1140 4902,-937.17
  text "ALL ARTWORK VIEWED FROM TOP SIDE" at -228.5,-655.67 h60
  text "BOARD #:" at 2248,-655.67 h60
  text ".PRJ_Number" at 2793.5,-655.67 h60
  text "REV:" at 3638,-655.67 h60
  text ".PCB_Rev" at 3929.5,-655.67 h60
  text "SVN REV:" at 4476,-655.67 h60
  text ".VersionControl_RevNumber" at 4982,-655.67 h60
  text "LAYER NAME =" at -228.5,-858.49 h60
  text "PLOT NAME =" at -228.5,-1064.34 h60
  text ".plot_File_Name" at 577,-1064.34 h60
  text "GENERATED    :" at 2250,-1064.34 h60
  text ".Print_Date" at 3119.5,-1064.34 h60
  text ".Print_Time" at 3848.5,-1064.34 h60
  text "TEXAS INSTRUMENTS" at 5113,-1064.34 h60
M12 Stackup:
  drawing of 1023 lines, arcs and shapes, not listed
  text "Layer" at 11455.88,10464.68 h60
  text "Name" at 11865.79,10464.68 h60
  text "Material" at 12795.54,10464.68 h60
  text "Thickness" at 13655.3,10464.68 h60
  text "Constant" at 14305.14,10464.68 h60
  text "Board Layer Stack" at 14875,10464.68 h60
  text "Top Overlay" at 11865.79,10344.68 h60
  text "Top Solder" at 11865.79,10224.68 h60
  text "Solder Resist" at 12795.54,10224.68 h60
  text "0.40mil" at 13655.3,10224.68 h60
  text "3.5" at 14305.14,10224.68 h60
  text "1" at 11455.88,10104.68 h60
  text "Top Layer" at 11865.79,10104.68 h60
  text "1.40mil" at 13655.3,10104.68 h60
  text "Dielectric 1" at 11865.79,9984.68 h60
  text "Megtron6" at 12795.54,9984.68 h60
  text "5.70mil" at 13655.3,9984.68 h60
  text "3.23" at 14305.14,9984.68 h60
  text "2" at 11455.88,9864.68 h60
  text "L2 GND" at 11865.79,9864.68 h60
  text "CF-004" at 12795.54,9864.68 h60
  text "1.40mil" at 13655.3,9864.68 h60
  text "Dielectric 3" at 11865.79,9744.68 h60
  text "FR4-370HR" at 12795.54,9744.68 h60
  text "3.00mil" at 13655.3,9744.68 h60
  text "3.72" at 14305.14,9744.68 h60
  text "3" at 11455.88,9624.68 h60
  text "L3 PWR" at 11865.79,9624.68 h60
  text "CF-004" at 12795.54,9624.68 h60
  text "2.76mil" at 13655.3,9624.68 h60
  text "Dielectric 5" at 11865.79,9504.68 h60
  text "FR4-370HR" at 12795.54,9504.68 h60
  text "3.00mil" at 13655.3,9504.68 h60
  text "3.86" at 14305.14,9504.68 h60
  text "4" at 11455.88,9384.68 h60
  text "L4 GND" at 11865.79,9384.68 h60
  text "CF-004" at 12795.54,9384.68 h60
  text "1.40mil" at 13655.3,9384.68 h60
  text "Dielectric 7" at 11865.79,9264.68 h60
  text "FR4-370HR" at 12795.54,9264.68 h60
  text "3.00mil" at 13655.3,9264.68 h60
  text "3.72" at 14305.14,9264.68 h60
  text "5" at 11455.88,9144.68 h60
  text "L5 PWR/SIG" at 11865.79,9144.68 h60
  text "CF-004" at 12795.54,9144.68 h60
  text "1.38mil" at 13655.3,9144.68 h60
  text "Dielectric 11" at 11865.79,9024.68 h60
  text "FR4-370HR" at 12795.54,9024.68 h60
  text "3.00mil" at 13655.3,9024.68 h60
  text "3.86" at 14305.14,9024.68 h60
  text "6" at 11455.88,8904.68 h60
  text "L6 GND" at 11865.79,8904.68 h60
  text "CF-004" at 12795.54,8904.68 h60
  text "1.38mil" at 13655.3,8904.68 h60
  text "Dielectric 15" at 11865.79,8784.68 h60
  text "FR4-370HR" at 12795.54,8784.68 h60
  text "4.80mil" at 13655.3,8784.68 h60
  text "3.92" at 14305.14,8784.68 h60
  text "7" at 11455.88,8664.68 h60
  text "L7 SIGNAL" at 11865.79,8664.68 h60
  text "CF-004" at 12795.54,8664.68 h60
  text "0.69mil" at 13655.3,8664.68 h60
  text "Dielectric 9" at 11865.79,8544.68 h60
  text "FR4-370HR" at 12795.54,8544.68 h60
  text "4.80mil" at 13655.3,8544.68 h60
  text "3.92" at 14305.14,8544.68 h60
  text "8" at 11455.88,8424.68 h60
  text "L8 GND" at 11865.79,8424.68 h60
  text "CF-004" at 12795.54,8424.68 h60
  text "1.38mil" at 13655.3,8424.68 h60
  text "Dielectric 13" at 11865.79,8304.68 h60
  text "FR4-370HR" at 12795.54,8304.68 h60
  text "4.80mil" at 13655.3,8304.68 h60
  text "3.92" at 14305.14,8304.68 h60
  text "9" at 11455.88,8184.68 h60
  text "L9 GND" at 11865.79,8184.68 h60
  text "CF-004" at 12795.54,8184.68 h60
  text "1.38mil" at 13655.3,8184.68 h60
  text "Dielectric1" at 11865.79,8064.68 h60
  text "FR4-370HR" at 12795.54,8064.68 h60
  text "4.80mil" at 13655.3,8064.68 h60
  text "3.92" at 14305.14,8064.68 h60
  text "10" at 11455.88,7944.68 h60
  text "L10 SIGNAL" at 11865.79,7944.68 h60
  text "CF-004" at 12795.54,7944.68 h60
  text "1.38mil" at 13655.3,7944.68 h60
  text "Dielectric 14" at 11865.79,7824.68 h60
  text "FR4-370HR" at 12795.54,7824.68 h60
  text "4.80mil" at 13655.3,7824.68 h60
  text "3.92" at 14305.14,7824.68 h60
  text "11" at 11455.88,7704.68 h60
  text "L11 GND" at 11865.79,7704.68 h60
  text "CF-004" at 12795.54,7704.68 h60
  text "1.38mil" at 13655.3,7704.68 h60
  text "Dielectric 10" at 11865.79,7584.68 h60
  text "FR4-370HR" at 12795.54,7584.68 h60
  text "4.80mil" at 13655.3,7584.68 h60
  text "3.92" at 14305.14,7584.68 h60
  text "12" at 11455.88,7464.68 h60
  text "L12 SIGNAL" at 11865.79,7464.68 h60
  text "CF-004" at 12795.54,7464.68 h60
  text "0.69mil" at 13655.3,7464.68 h60
  text "Dielectric 16" at 11865.79,7344.68 h60
  text "FR4-370HR" at 12795.54,7344.68 h60
  text "4.80mil" at 13655.3,7344.68 h60
  text "3.92" at 14305.14,7344.68 h60
  text "13" at 11455.88,7224.68 h60
  text "L13 GND" at 11865.79,7224.68 h60
  text "CF-004" at 12795.54,7224.68 h60
  text "1.38mil" at 13655.3,7224.68 h60
  text "Dielectric 12" at 11865.79,7104.68 h60
  text "FR4-370HR" at 12795.54,7104.68 h60
  text "3.00mil" at 13655.3,7104.68 h60
  text "3.86" at 14305.14,7104.68 h60
  text "14" at 11455.88,6984.68 h60
  text "L14 PWR" at 11865.79,6984.68 h60
  text "CF-004" at 12795.54,6984.68 h60
  text "1.38mil" at 13655.3,6984.68 h60
  text "Dielectric 8" at 11865.79,6864.68 h60
  text "FR4-370HR" at 12795.54,6864.68 h60
  text "3.00mil" at 13655.3,6864.68 h60
  text "3.72" at 14305.14,6864.68 h60
  text "15" at 11455.88,6744.68 h60
  text "L15 GND" at 11865.79,6744.68 h60
  text "CF-004" at 12795.54,6744.68 h60
  text "1.40mil" at 13655.3,6744.68 h60
  text "Dielectric 6" at 11865.79,6624.68 h60
  text "FR4-370HR" at 12795.54,6624.68 h60
  text "3.00mil" at 13655.3,6624.68 h60
  text "3.86" at 14305.14,6624.68 h60
  text "16" at 11455.88,6504.68 h60
  text "L16 PWR/SIG" at 11865.79,6504.68 h60
  text "CF-004" at 12795.54,6504.68 h60
  text "2.76mil" at 13655.3,6504.68 h60
  text "Dielectric 4" at 11865.79,6384.68 h60
  text "FR4-370HR" at 12795.54,6384.68 h60
  text "3.00mil" at 13655.3,6384.68 h60
  text "3.72" at 14305.14,6384.68 h60
  text "17" at 11455.88,6264.68 h60
  text "L16 GND" at 11865.79,6264.68 h60
  text "CF-004" at 12795.54,6264.68 h60
  text "1.40mil" at 13655.3,6264.68 h60
  text "Dielectric 2" at 11865.79,6144.68 h60
  text "Megtron6" at 12795.54,6144.68 h60
  text "5.70mil" at 13655.3,6144.68 h60
  text "3.23" at 14305.14,6144.68 h60
  text "18" at 11455.88,6024.68 h60
  text "Bottom Layer" at 11865.79,6024.68 h60
  text "1.40mil" at 13655.3,6024.68 h60
  text "Bottom Solder" at 11865.79,5904.68 h60
  text "Solder Resist" at 12795.54,5904.68 h60
  text "0.40mil" at 13655.3,5904.68 h60
  text "3.5" at 14305.14,5904.68 h60
  text "Bottom Overlay" at 11865.79,5784.68 h60
  text "Total board thickness:" at 11455.88,5664.68 h60
  text "96.11mil" at 13655.3,5664.68 h60
  text ".Layer_Name" at 577,-858.49 h60
M13 Component Bodies Top:
  text ".Layer_Name" at 577,-858.49 h60
M14 Component Bodies Bottom:
  text ".Layer_Name" at 577,-858.49 h60
M15 Courtyards Top:
  text ".Layer_Name" at 577,-858.49 h60
M16 Courtyards Bottom:
  text ".Layer_Name" at 577,-858.49 h60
